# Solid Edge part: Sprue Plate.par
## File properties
Author: Dan
Template: metric part.par
Last saved by: Dan
Revision: 8
Application: Solid Edge
Density: 7833.000 kg/m^3
Accuracy: 0.990
Material: Steel
Face Style: Steel
Fill Style: ANSI32(Steel)
Virtual Style: Machined steel
Coef. of Thermal Exp: 1.3e-05
Thermal Conductivity: 32.0
Specific Heat: 481.0
Modulus of Elasticity: 199947953000.0
Poisson's Ratio: 0.29
Yield Stress: 262000766.0
Ultimate Stress: 358527364.0
Elongation: 0.0
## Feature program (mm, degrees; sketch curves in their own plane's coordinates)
sketch for "unnamed Protrusion 1" plane through (0, 0, 0) normal (0, 0, 1) x-axis (1, 0, 0)
extrude "unnamed Protrusion 1" add finite 7 along -normal
sketch for "Hole_6" plane through (0, 0, -7) normal (0, 0, -1) x-axis (1, 0, 0)
hole "Hole_6" diameter 6.5 through  CounterBoreDepth = 6.5 mm
sketch for "unnamed Hole 1" plane through (0, 0, -7) normal (0, 0, -1) x-axis (1, 0, 0)
  hole centre (36, 0) bore radius 3.25
hole "unnamed Hole 1" through
sketch for "unnamed Hole 2" plane through (0, 0, -7) normal (0, 0, -1) x-axis (1, 0, 0)
  circle centre (0, 0) radius 42.5
hole "unnamed Hole 2" through
sketch for "unnamed Hole 3" plane through (0, 0, -7) normal (0, 0, -1) x-axis (1, 0, 0)
hole "unnamed Hole 3" through
pattern "unnamed Pattern 1" of "Hole_6", "unnamed Hole 1", "unnamed Hole 2", "unnamed Hole 3"
sketch for "unnamed RevolvedCutout 1" plane through (0, 0, 0) normal (1, 0, 0) x-axis (0, 1, 0)
revolve "unnamed RevolvedCutout 1" cut finite 360 deg about sketch line (0, 35) -> (0, -5)
sketch for "Hole_5" plane through (0, 0, -7) normal (0, 0, -1) x-axis (1, 0, 0)
hole "Hole_5" diameter 4 through  VBottomAngle = 118 deg
sketch for "unnamed RevolvedCutout 2" plane through (0, 0, 0) normal (0, -1, 0) x-axis (1, 0, 0)
revolve "unnamed RevolvedCutout 2" cut finite 360 deg
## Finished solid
Body 1: solid body, 18 faces, 22 edges, 0 vertices.
  Faces by surface: cylinder 10, plane 6, cone 1, sphere 1
  Edges by curve: circle 22
Bounding box of the edges (mm; curved faces can reach further): 85.000 x 85.000 x 7.000, from (-42.5, -42.5, -7) to (42.5, 42.5, 0).
Cylindrical faces by radius (mm): R2 x1, R3.25 x4, R5.75 x4, R42.5 x1
Conical faces (half-angle, radius in mm at the cone's reference point): 60 deg R2 x1
Spherical faces by radius (mm): R20 x1
Planar faces by outward normal: +z 1, -z 5
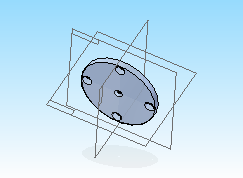
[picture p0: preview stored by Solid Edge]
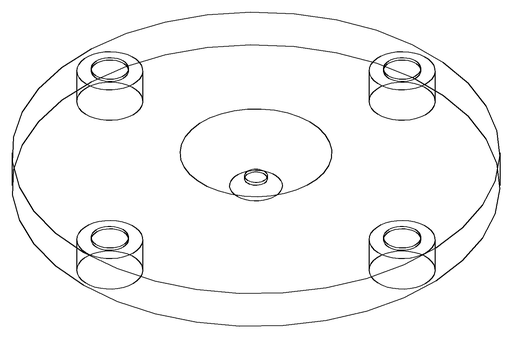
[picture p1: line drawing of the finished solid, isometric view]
